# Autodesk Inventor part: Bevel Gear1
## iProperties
Created: 2008-07
Part Number: Bevel Gear1
Material: Steel, Mild
Document SubType Name: Modeling
Designer: tangg
Categories: <?xml version="1.0" encoding="UTF-16"?> <MemberInstance><Categories><FamilyTemplate><FamilyTemplateParameter ValueType="xs:double" Id="1" ObjectReferenceKey="da
Mass: 34.1086 g
Surface Area: 24.6716 cm^2
Volume: 4.33952 cm^3
Density: 7.86 g/cm^3
CustomPartVersion: 1
Author: tangg
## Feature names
1. Teeth Body [Revolution]
2. Loft
3. Circular Pattern
4. Loft Right
5. Circular Pattern Right
6. Loft Left
7. Circular Pattern Left
8. Fix Body [Revolution]
